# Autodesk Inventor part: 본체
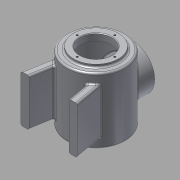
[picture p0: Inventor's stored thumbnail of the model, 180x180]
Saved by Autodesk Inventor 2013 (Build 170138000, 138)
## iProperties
Created: 2015-01
Part Number: 본체
Material: 알루미늄 6061
Document SubType Name: Modeling
Designer: Administrator
Mass: 1021.13 g
Surface Area: 1060.37 cm^2
Volume: 376.8 cm^3
Density: 2.71 g/cm^3
Author: Administrator
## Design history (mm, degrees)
sketch "스케치1"
  geometry: C1 r 50 at (0, 0); 1 further point
  constraints: 1 centre point, 1 coincident
  dimensions: "d0" = 50 radius of C1
extrude "돌출1" new body sketch "스케치1" stored distance "d1" = 112; taper "d2" = 0 deg
hole "구멍1" diameter "d6" = 54; stored, may be unused: countersink angle "d10" = 90 deg, drill point angle "d12" = 0 deg; dims "d4" = 10, "d5" = 10, "d7" = 6, "d8" = 54, "d9" = 8, "d11" = 8
sketch "스케치2"
  geometry: C1 r 45 at (0, 0); 1 further point
  constraints: 1 centre point, 1 coincident
  dimensions: "d13" = 45 radius of C1
extrude "돌출2" cut sketch "스케치2" distance "d14" = 97; taper "d15" = 0 deg
hole "구멍2" diameter "d18" = 54; stored, may be unused: countersink angle "d22" = 90 deg, drill point angle "d24" = 0 deg; dims "d16" = 10, "d17" = 10, "d19" = 6, "d20" = 54, "d21" = 8, "d23" = 8
sketch "스케치3"
  geometry: C1 r 38 at (0, 0); C2 r 27 at (0, 0) reference; 1 further point
  constraints: 1 centre point, 1 coincident
  dimensions: "d25" = 38 radius of C1
extrude "돌출3" join sketch "스케치3" distance "d26" = 5; taper "d27" = 0 deg
node "작업 평면1"
sketch "스케치4"
  geometry: C1 r 38 at (0, 0); 1 further point
  constraints: 1 centre point, 1 coincident
  dimensions: "d29" = 38 radius of C1
extrude "돌출4" join sketch "스케치4" stored distance "d30" = 5; taper "d31" = 0 deg
hole "구멍3" diameter "d34" = 54; stored, may be unused: countersink angle "d38" = 90 deg, drill point angle "d40" = 0 deg; dims "d32" = 10, "d33" = 10, "d35" = 6, "d36" = 54, "d37" = 8, "d39" = 30
sketch "스케치5"
  geometry: L1 (-138.91, -80)-(142.644, -80); L2 (-39.336, -30.865)-(-48, -80); L3 (-48, -80)-(-34, -80); L4 (-34, -80)-(-27.282, -41.901); L5 (0, 90.152)-(0, -105.867); L6 (39.336, -30.865)-(48, -80); L7 (48, -80)-(34, -80); L8 (34, -80)-(27.282, -41.901); A1 r 50 centre (0, 0) between (-39.336, -30.865) and (-27.282, -41.901); A2 r 50 centre (0, 0) between (27.282, -41.901) and (39.336, -30.865); 2 further points
  constraints: 16 end point, 4 point on circle, 4 symmetric about line, 3 point on line, 2 centre point, 1 coincident, 1 horizontal, 1 parallel, 1 perpendicular, 3 other
  dimensions: "d41" = 80 distance from line of point (0, 0) L1; "d42" = 14 distance of L2.end L3.end; "d43" = 48 horizontal distance of point (0, 0) L2.end; "d44" = 80 deg angle of L1 L4
extrude "돌출5" join sketch "스케치5" stored distance "d45" = 80; taper "d46" = 0 deg
sketch "스케치6"
  geometry: 5 further points
  constraints: 5 other
  dimensions: "d47" = 32 distance of point (0, 0) point (32, 0); "d48" = 0 vertical distance of point (32, 0) point (0, 0); "d51" = 360 deg dimension on point (0, 0) point (32, 0) (derived)
hole "구멍4" sketch "스케치6" at (32, 0), (0, 32), (-32, 0), (0, -32) diameter "d53" = 3.242; stored, may be unused: countersink angle "d57" = 90 deg, drill point angle "d59" = 118 deg; dims "d54" = 8, "d55" = 54, "d56" = 8, "d58" = 10
sketch "스케치7"
  geometry: 5 further points
  constraints: 1 vertical alignment, 5 other
  dimensions: "d63" = 360 deg dimension on point (0, 0) point (0, 32) (derived); "d88" = 32 distance of point (32, 0) point (0, 0)
hole "구멍5" sketch "스케치7" at (0, 32), (-32, 0), (0, -32), (32, 0) diameter "d65" = 3.242; stored, may be unused: countersink angle "d69" = 90 deg, drill point angle "d71" = 118 deg; dims "d66" = 8, "d67" = 54, "d68" = 8, "d70" = 10
node "작업 평면3"
  node "작업 평면2"
sketch "스케치8"
  geometry: L1 (-6, -26)-(6, -26); L2 (6, -26)-(6, 28); L3 (6, 28)-(-6, 28); L4 (-6, 28)-(-6, -26); L5 (-70.447, 1)-(22.592, 1); L6 (38, -61)-(-38, -61) reference; 1 further point
  constraints: 10 end point, 2 parallel, 2 perpendicular, 1 horizontal
  dimensions: "d73" = 12 distance between parallel lines of L2 L4; "d75" = 6 distance from line of L4 point (0, 0); "d76" = 54 distance of L3.end L1.start; "d77" = 27 distance between parallel lines of L3 L5; "d78" = 62 distance between parallel lines of L6 L5
extrude "돌출6" join sketch "스케치8" stored distance "d79" = 80; taper "d80" = 0 deg
sketch "스케치9"
  geometry: L1 (-26, -6)-(28, -6) reference; L2 (28, -6)-(28, 6) reference; 4 further points
  constraints: 2 midpoint, 1 horizontal alignment, 1 vertical alignment, 1 other
feature "엠보싱1" sketch "스케치9" dims "d81" = 0.5, "d82" = 0
fillet "모깎기1" dims "d83" = 3
fillet "모깎기2" dims "d84" = 3
fillet "모깎기3" dims "d85" = 3
fillet "모깎기4" dims "d86" = 3
fillet "모깎기5" dims "d87" = 3
chamfer "모따기1" distance "d89" = 1; stored, may be unused: second distance "d90" = 2, angle "d91" = 45 deg
fillet "모깎기6" dims "d92" = 3
node "솔리드1"
mirror "대칭1"
mirror "대칭2"
other parameters: "d28" = 62, "d72" = -2
